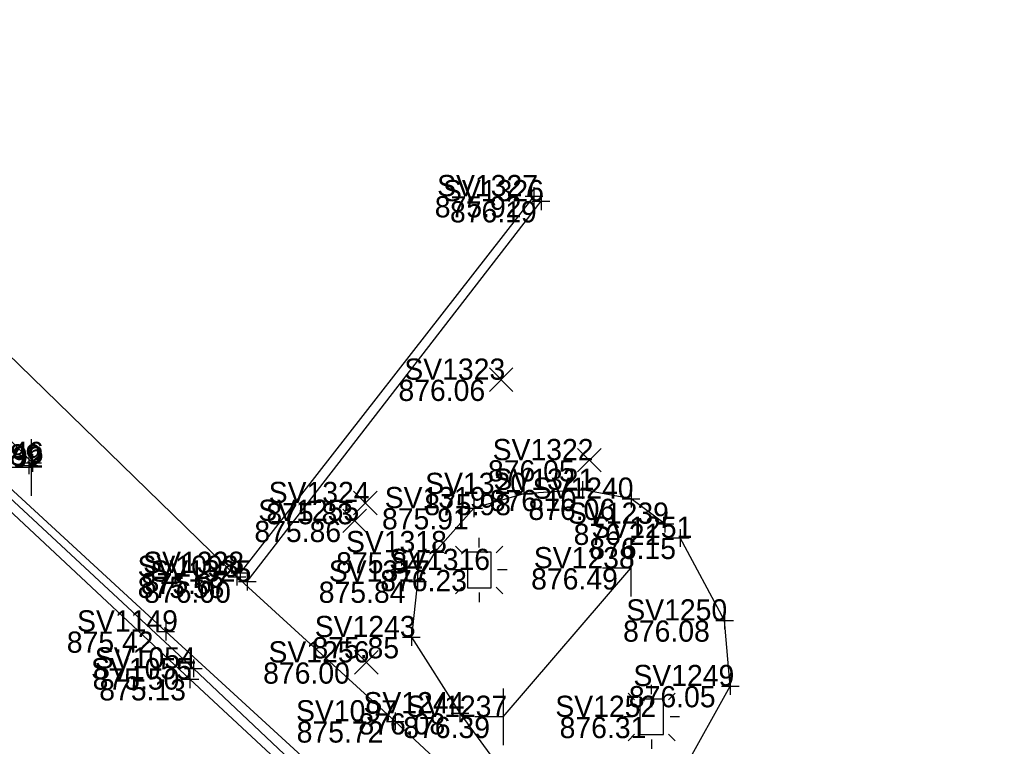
# Model space of a CAD drawing. Extents: x 1480001 to 1480402, y 379235 to 379603.
# Drawn here: x 1480223.3 to 1480278.2, y 379391.7 to 379432.9 of the extents above; entities that cross this region are included whole.
import ezdxf

# ---------------------------------------------------------------- set-up
doc = ezdxf.new("R2010")
doc.units = 0
for name, color, linetype in [('Default', 7, 'Continuous'), ('PV_X_Curb', 7, 'Continuous'), ('PV_X_Driveway', 7, 'Continuous'), ('PV_X_Walk', 7, 'Continuous'), ('RD_X_Cells', 7, 'Continuous'), ('SN_X_Public', 7, 'Continuous'), ('SV_X_Random_Point', 7, 'Continuous'), ('SV_X_Shot_Marker', 7, 'Continuous'), ('SV_X_Text_Elevation', 7, 'Continuous'), ('SV_X_Text_Name', 7, 'Continuous'), ('UT_X_Water', 7, 'Continuous'), ('VG_X_Flower_Bed', 7, 'Continuous')]:
    doc.layers.add(name, color=color, linetype=linetype)

msp = doc.modelspace()

# ---------------------------------------------------------------- linework, layer by layer
at = {"layer": 'Default'}
msp.add_line((1480250.68, 379393.41), (1480257.907, 379401.814), dxfattribs=at)
at = {"layer": 'PV_X_Curb'}
msp.add_line((1480236.201, 379401.061), (1480252.83, 379422.58), dxfattribs=at)
for points in [[(1480221.908, 379406.565), (1480233.156, 379396.15), (1480249.934, 379380.311), (1480262.014, 379368.886), (1480262.346, 379369.254), (1480264.513, 379367.165), (1480266.627, 379365.06), (1480266.41, 379364.736), (1480284.493, 379347.537), (1480298.919, 379333.838), (1480300.736, 379332.585), (1480315.855, 379318.308), (1480323.784, 379310.749), (1480324.548, 379310.084), (1480343.241, 379292.305), (1480360.288, 379276.242)], [(1480221.495, 379406.235), (1480232.955, 379395.538), (1480249.633, 379380.044), (1480261.648, 379368.645), (1480263.97, 379366.423), (1480266.337, 379364.241), (1480284.168, 379347.237), (1480298.679, 379333.414), (1480300.396, 379332.229), (1480315.326, 379318.045), (1480323.87, 379309.98), (1480343.087, 379291.663), (1480360.248, 379275.585)]]:
    msp.add_lwpolyline(points, dxfattribs=at)
at = {"layer": 'PV_X_Driveway'}
msp.add_line((1480252.425, 379422.865), (1480235.8, 379401.552), dxfattribs=at)
at = {"layer": 'PV_X_Walk'}
msp.add_lwpolyline([(1480355.123, 379297.828), (1480351.285, 379293.6), (1480334.098, 379309.328), (1480328.212, 379315.428), (1480328.737, 379316.329), (1480319.905, 379324.485), (1480307.606, 379335.13), (1480302.895, 379338.359), (1480281.823, 379358.406), (1480285.611, 379363.387), (1480280.441, 379367.109), (1480277.224, 379362.834), (1480260.819, 379378.019), (1480244.572, 379393.153), (1480235.613, 379401.335), (1480215.341, 379421.047)], dxfattribs=at)
at = {"layer": 'RD_X_Cells'}
for p, q in [((1480248.365, 379402.685), (1480247.995, 379403.06)), ((1480249.33, 379402.997), (1480249.33, 379403.529)), ((1480250.663, 379403.06), (1480250.292, 379402.685)), ((1480248.287, 379401.724), (1480247.755, 379401.724)), ((1480249.33, 379401.717), (1480249.33, 379401.717)), ((1480250.905, 379401.724), (1480250.372, 379401.724)), ((1480248.365, 379400.749), (1480247.995, 379400.374)), ((1480249.33, 379400.437), (1480249.33, 379399.905)), ((1480250.663, 379400.374), (1480250.292, 379400.749)), ((1480259.085, 379394.685), (1480259.085, 379395.217)), ((1480258.12, 379394.373), (1480257.75, 379394.748)), ((1480260.418, 379394.748), (1480260.047, 379394.373)), ((1480258.042, 379393.412), (1480257.51, 379393.412)), ((1480259.085, 379393.405), (1480259.085, 379393.405)), ((1480260.66, 379393.412), (1480260.127, 379393.412)), ((1480258.12, 379392.437), (1480257.75, 379392.062)), ((1480259.085, 379392.125), (1480259.085, 379391.593)), ((1480260.418, 379392.062), (1480260.047, 379392.437))]:
    msp.add_line(p, q, dxfattribs=at)
for points in [[(1480248.663, 379400.717), (1480249.995, 379400.717), (1480249.995, 379402.717), (1480248.663, 379402.717)], [(1480258.418, 379392.405), (1480259.75, 379392.405), (1480259.75, 379394.405), (1480258.418, 379394.405)]]:
    msp.add_lwpolyline(points, close=True, dxfattribs=at)
at = {"layer": 'SN_X_Public'}
for p, q in [((1480223.98, 379409.114), (1480223.98, 379405.914)), ((1480223.98, 379407.514), (1480222.38, 379407.514)), ((1480257.907, 379403.414), (1480257.907, 379400.214)), ((1480257.907, 379401.814), (1480256.307, 379401.814)), ((1480250.68, 379395.01), (1480250.68, 379391.81)), ((1480250.68, 379393.41), (1480249.08, 379393.41))]:
    msp.add_line(p, q, dxfattribs=at)
at = {"layer": 'SV_X_Random_Point'}
for p, q in [((1480249.901, 379411.812), (1480251.235, 379413.147)), ((1480249.901, 379413.147), (1480251.235, 379411.812)), ((1480254.89, 379407.263), (1480256.224, 379408.598)), ((1480254.89, 379408.598), (1480256.224, 379407.263)), ((1480242.217, 379404.837), (1480243.551, 379406.172)), ((1480242.217, 379406.172), (1480243.551, 379404.837)), ((1480241.616, 379403.83), (1480242.95, 379405.165)), ((1480241.616, 379405.165), (1480242.95, 379403.83)), ((1480242.272, 379395.819), (1480243.606, 379397.154)), ((1480242.272, 379397.154), (1480243.606, 379395.819))]:
    msp.add_line(p, q, dxfattribs=at)
at = {"layer": 'SV_X_Shot_Marker'}
for p, q in [((1480251.925, 379422.865), (1480252.925, 379422.865)), ((1480252.425, 379423.365), (1480252.425, 379422.365)), ((1480252.425, 379422.865), (1480252.425, 379422.865)), ((1480252.83, 379423.08), (1480252.83, 379422.08)), ((1480252.33, 379422.58), (1480253.33, 379422.58)), ((1480252.83, 379422.58), (1480252.83, 379422.58)), ((1480223.846, 379408.129), (1480223.846, 379407.129)), ((1480224.057, 379408.27), (1480224.057, 379407.27)), ((1480223.346, 379407.629), (1480224.346, 379407.629)), ((1480223.557, 379407.77), (1480224.557, 379407.77)), ((1480223.846, 379407.629), (1480223.846, 379407.629)), ((1480224.057, 379407.77), (1480224.057, 379407.77)), ((1480251.852, 379406.517), (1480251.852, 379405.517)), ((1480255.177, 379406.749), (1480255.177, 379405.749)), ((1480251.352, 379406.017), (1480252.352, 379406.017)), ((1480251.852, 379406.017), (1480251.852, 379406.017)), ((1480254.677, 379406.249), (1480255.677, 379406.249)), ((1480255.177, 379406.249), (1480255.177, 379406.249)), ((1480257.924, 379406.248), (1480257.924, 379405.248)), ((1480249.014, 379405.714), (1480249.014, 379404.714)), ((1480257.424, 379405.748), (1480258.424, 379405.748)), ((1480257.924, 379405.748), (1480257.924, 379405.748)), ((1480248.514, 379405.214), (1480249.514, 379405.214)), ((1480249.014, 379405.214), (1480249.014, 379405.214)), ((1480259.84, 379404.835), (1480259.84, 379403.835)), ((1480259.34, 379404.335), (1480260.34, 379404.335)), ((1480259.84, 379404.335), (1480259.84, 379404.335)), ((1480260.704, 379404.035), (1480260.704, 379403.035)), ((1480246.824, 379403.225), (1480246.824, 379402.225)), ((1480260.204, 379403.535), (1480261.204, 379403.535)), ((1480260.704, 379403.535), (1480260.704, 379403.535)), ((1480246.324, 379402.725), (1480247.324, 379402.725)), ((1480246.824, 379402.725), (1480246.824, 379402.725)), ((1480235.8, 379402.052), (1480235.8, 379401.052)), ((1480235.3, 379401.552), (1480236.3, 379401.552)), ((1480235.613, 379401.835), (1480235.613, 379400.835)), ((1480235.8, 379401.552), (1480235.8, 379401.552)), ((1480236.201, 379401.561), (1480236.201, 379400.561)), ((1480245.84, 379401.559), (1480245.84, 379400.559)), ((1480235.113, 379401.335), (1480236.113, 379401.335)), ((1480235.613, 379401.335), (1480235.613, 379401.335)), ((1480235.701, 379401.061), (1480236.701, 379401.061)), ((1480236.201, 379401.061), (1480236.201, 379401.061)), ((1480245.34, 379401.059), (1480246.34, 379401.059)), ((1480245.84, 379401.059), (1480245.84, 379401.059)), ((1480263.215, 379399.361), (1480263.215, 379398.361)), ((1480231.592, 379398.737), (1480231.592, 379397.737)), ((1480262.715, 379398.861), (1480263.715, 379398.861)), ((1480263.215, 379398.861), (1480263.215, 379398.861)), ((1480231.092, 379398.237), (1480232.092, 379398.237)), ((1480231.592, 379398.237), (1480231.592, 379398.237)), ((1480245.489, 379398.42), (1480245.489, 379397.42)), ((1480244.989, 379397.92), (1480245.989, 379397.92)), ((1480245.489, 379397.92), (1480245.489, 379397.92)), ((1480233.156, 379396.65), (1480233.156, 379395.65)), ((1480232.656, 379396.15), (1480233.656, 379396.15)), ((1480232.955, 379396.038), (1480232.955, 379395.038)), ((1480233.156, 379396.15), (1480233.156, 379396.15)), ((1480232.455, 379395.538), (1480233.455, 379395.538)), ((1480232.955, 379395.538), (1480232.955, 379395.538)), ((1480263.531, 379395.65), (1480263.531, 379394.65)), ((1480263.031, 379395.15), (1480264.031, 379395.15)), ((1480263.531, 379395.15), (1480263.531, 379395.15)), ((1480248.239, 379394.11), (1480248.239, 379393.11)), ((1480244.572, 379393.653), (1480244.572, 379392.653)), ((1480247.739, 379393.61), (1480248.739, 379393.61)), ((1480248.239, 379393.61), (1480248.239, 379393.61)), ((1480244.072, 379393.153), (1480245.072, 379393.153)), ((1480244.572, 379393.153), (1480244.572, 379393.153))]:
    msp.add_line(p, q, dxfattribs=at)
at = {"layer": 'UT_X_Water'}
msp.add_line((1480224.057, 379407.77), (1480199.329, 379432.864), dxfattribs=at)
msp.add_lwpolyline([(1480212.628, 379415.684), (1480231.592, 379398.237), (1480249.493, 379381.828), (1480253.44, 379378.963), (1480259.284, 379374.539), (1480264.171, 379372.865), (1480269.434, 379369.248), (1480270.598, 379368.157), (1480270.755, 379365.904), (1480271.186, 379363.733), (1480285.468, 379347.959), (1480298.848, 379335.614), (1480313.013, 379322.705), (1480330.745, 379305.601), (1480344.344, 379292.312), (1480351.783, 379285.136)], dxfattribs=at)
at = {"layer": 'VG_X_Flower_Bed'}
msp.add_lwpolyline([(1480259.84, 379404.335), (1480257.924, 379405.748), (1480255.177, 379406.249), (1480251.852, 379406.017), (1480249.014, 379405.214), (1480246.824, 379402.725), (1480245.84, 379401.059), (1480245.489, 379397.92), (1480248.239, 379393.61), (1480250.763, 379390.17), (1480253.969, 379388.413), (1480257.154, 379388.076), (1480260.916, 379390.426), (1480263.531, 379395.15), (1480263.215, 379398.861), (1480260.704, 379403.535)], dxfattribs=at)

# ---------------------------------------------------------------- texts
at = {"layer": 'SV_X_Text_Elevation'}
for s, p in [('875.92', (1480246.813, 379421.665)), ('876.19', (1480247.672, 379421.38)), ('876.06', (1480244.757, 379411.28)), ('876.05', (1480249.822, 379406.73)), ('875.98', (1480246.221, 379404.817)), ('876.10', (1480249.924, 379405.049)), ('875.83', (1480237.281, 379404.304)), ('876.06', (1480252.113, 379404.548)), ('875.91', (1480243.826, 379404.014)), ('875.86', (1480236.605, 379403.298)), ('876.21', (1480254.671, 379403.135)), ('876.15', (1480255.555, 379402.335)), ('875.84', (1480241.231, 379401.525)), ('875.67', (1480230.178, 379400.352)), ('876.23', (1480243.727, 379400.517)), ('876.49', (1480252.266, 379400.614)), ('875.58', (1480230.001, 379400.135)), ('876.00', (1480230.362, 379399.861)), ('875.84', (1480240.247, 379399.859)), ('876.08', (1480257.47, 379397.661)), ('875.42', (1480225.989, 379397.037)), ('875.85', (1480239.886, 379396.72)), ('876.00', (1480237.1, 379395.287)), ('875.50', (1480227.449, 379394.95)), ('875.13', (1480227.825, 379394.338)), ('876.05', (1480257.796, 379393.95)), ('876.08', (1480242.494, 379392.41)), ('876.39', (1480245.03, 379392.21)), ('876.31', (1480253.878, 379392.205)), ('875.72', (1480238.998, 379391.953))]:
    msp.add_text(s, height=1.2, dxfattribs=at).set_placement(p)
at = {"layer": 'SV_X_Text_Name'}
for s, p in [('SV1327', (1480246.946, 379422.865)), ('SV1326', (1480247.275, 379422.58)), ('SV1323', (1480245.089, 379412.48)), ('SV1322', (1480250.087, 379407.93)), ('SV1189', (1480218.83, 379407.629)), ('SV1192', (1480218.964, 379407.514)), ('SV1146', (1480218.966, 379407.77)), ('SV1321', (1480250.132, 379406.249)), ('SV1320', (1480246.269, 379406.017)), ('SV1240', (1480252.35, 379405.748)), ('SV1324', (1480237.414, 379405.504)), ('SV1319', (1480243.979, 379405.214)), ('SV1255', (1480236.823, 379404.498)), ('SV1239', (1480254.351, 379404.335)), ('SV1251', (1480255.677, 379403.535)), ('SV1318', (1480241.789, 379402.725)), ('SV1098', (1480229.992, 379401.335)), ('SV1328', (1480230.311, 379401.552)), ('SV1316', (1480244.229, 379401.717)), ('SV1238', (1480252.418, 379401.814)), ('SV1325', (1480230.722, 379401.061)), ('SV1317', (1480240.815, 379401.059)), ('SV1250', (1480257.651, 379398.861)), ('SV1149', (1480226.567, 379398.237)), ('SV1243', (1480240.019, 379397.92)), ('SV1256', (1480237.403, 379396.487)), ('SV1054', (1480227.573, 379396.15)), ('SV1055', (1480227.362, 379395.538)), ('SV1249', (1480258.052, 379395.15)), ('SV1244', (1480242.779, 379393.61)), ('SV1097', (1480238.96, 379393.153)), ('SV1237', (1480245.201, 379393.41)), ('SV1252', (1480253.634, 379393.405))]:
    msp.add_text(s, height=1.2, dxfattribs=at).set_placement(p)

doc.saveas('drawing.dxf')
